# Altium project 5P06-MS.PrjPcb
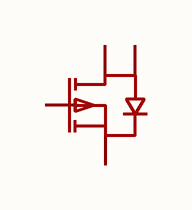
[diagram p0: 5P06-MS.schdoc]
1 sheet, 1 parts. Net scope: global (net labels, ports and power ports of the same name join across sheets).

## Sheet 5P06-MS.schdoc
size 127 x 101 mm

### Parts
Q?  5p06-ms  [SOT-223-3_L6.5-W3.4-P2.30-LS7.0-BR]  (value not drawn)

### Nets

Not connected (* = marked no-connect by the designer): Q? 1(G) 2(D) 3(S) 4(D)

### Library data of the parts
Q? = 5p06-ms: 数量:1个P沟道;漏源电压(Vdss):60V;连续漏极电流(Id):5A;导通电阻(RDS(on)):110mΩ@10V;耗散功率(Pd):1W;阈值电压(Vgs(th)):1.5V;; Manufacturer: MSKSEMI(美森科); AddInBom: yes; ModelId: 925194bf9823436183a3e0b978a8d076; ModelName: SOT-223-4P_L6.5-W3.5-H1.6-LS7.0-P2.30; ModelTransform: 279.89794,255.905,0,180,0,0,-3.9385,-0.0005,0; Number: 1个P沟道; Drain to Source Voltage: 60V; Current - Continuous Drain(Id): 5A; Pd - Power Dissipation: 1W; Gate Threshold Voltage (Vgs(th)): 1.5V; Gate Charge(Qg): 5.4nC@10V; Input Capacitance(Ciss): 310pF; Reverse Transfer Capacitance (Crss@Vds): 15pF; Type: P沟道; Output Capacitance(Coss): 22pF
